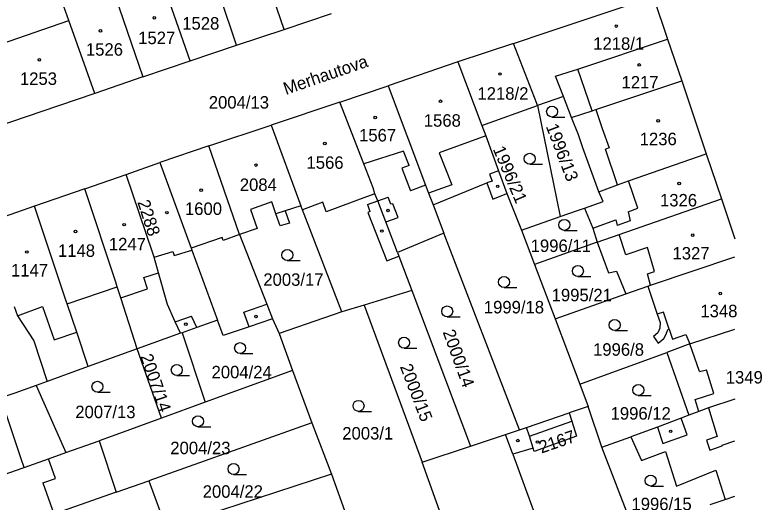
# Model space of a CAD drawing. Extents: x -564952 to -564307, y -1202373 to -1201847.
# Drawn here: x -564412.8 to -564310.9, y -1202215.7 to -1202149.3 of the extents above; entities that cross this region are included whole.
import ezdxf

# ---------------------------------------------------------------- set-up
doc = ezdxf.new("R2010")
doc.units = 0
for name, color, linetype in [('Hranice parcel', 7, 'Continuous'), ('Parcelní čísla', 7, 'Continuous'), ('Pop  PČ popisy', 7, 'Continuous'), ('Vnitřní kresba', 7, 'Continuous'), ('Značky budov', 7, 'Continuous'), ('Značky kultur', 7, 'Continuous')]:
    doc.layers.add(name, color=color, linetype=linetype)

msp = doc.modelspace()

# ---------------------------------------------------------------- linework, layer by layer
at = {"layer": 'Hranice parcel'}
for p, q in [((-564325.78, -1202146.73), (-564323.81, -1202152.55)), ((-564376.1, -1202151.25), (-564369.64, -1202149.05)), ((-564382.59, -1202153.39), (-564376.1, -1202151.25)), ((-564323.81, -1202152.55), (-564321.87, -1202158.24)), ((-564388.94, -1202155.54), (-564382.59, -1202153.39)), ((-564344.81, -1202153.14), (-564352.41, -1202155.68)), ((-564395.37, -1202157.69), (-564388.94, -1202155.54)), ((-564352.41, -1202155.68), (-564361.94, -1202158.92)), ((-564352.41, -1202155.68), (-564349.13, -1202164.34)), ((-564395.37, -1202157.69), (-564401.92, -1202159.96)), ((-564368.52, -1202161.14), (-564361.94, -1202158.92)), ((-564321.87, -1202158.24), (-564318.53, -1202168.2)), ((-564338.02, -1202160.39), (-564341.55, -1202161.62)), ((-564336.91, -1202163.24), (-564338.02, -1202160.39)), ((-564368.52, -1202161.14), (-564377.89, -1202164.3)), ((-564349.13, -1202164.34), (-564341.55, -1202161.62)), ((-564341.55, -1202161.62), (-564338.44, -1202176.75)), ((-564386.36, -1202167.12), (-564377.89, -1202164.3)), ((-564377.89, -1202164.3), (-564373.81, -1202175.3)), ((-564386.36, -1202167.12), (-564393.08, -1202169.4)), ((-564382.19, -1202179.19), (-564386.36, -1202167.12)), ((-564318.53, -1202168.2), (-564316.45, -1202174.31)), ((-564397.64, -1202171), (-564393.08, -1202169.4)), ((-564393.08, -1202169.4), (-564388.79, -1202181.06)), ((-564403.3, -1202172.98), (-564397.64, -1202171)), ((-564394.02, -1202181.72), (-564397.64, -1202171)), ((-564403.3, -1202172.98), (-564410.14, -1202175.34)), ((-564399.08, -1202185.67), (-564403.3, -1202172.98)), ((-564356.41, -1202173.55), (-564355.8, -1202175.14)), ((-564345.72, -1202173.6), (-564343.72, -1202178.62)), ((-564373.81, -1202175.3), (-564375.97, -1202175.98)), ((-564355.8, -1202175.14), (-564354.32, -1202179)), ((-564316.45, -1202174.31), (-564314.65, -1202179.77)), ((-564410.14, -1202175.34), (-564416.78, -1202177.62)), ((-564405.82, -1202188.28), (-564410.14, -1202175.34)), ((-564343.72, -1202178.62), (-564338.44, -1202176.75)), ((-564354.32, -1202179), (-564360.64, -1202181.66)), ((-564344.02, -1202205.84), (-564354.32, -1202179)), ((-564343.72, -1202178.62), (-564341.96, -1202183.28)), ((-564333.4, -1202180.24), (-564341.96, -1202183.28)), ((-564360.64, -1202181.66), (-564360.46, -1202182.13)), ((-564360.46, -1202182.13), (-564358.7, -1202186.81)), ((-564341.96, -1202183.28), (-564339.15, -1202190.71)), ((-564329.51, -1202187.3), (-564326.5, -1202186.24)), ((-564358.7, -1202186.81), (-564365.21, -1202188.81)), ((-564358.7, -1202186.81), (-564350.69, -1202208.05)), ((-564339.15, -1202190.71), (-564329.51, -1202187.3)), ((-564365.21, -1202188.81), (-564368.26, -1202189.75)), ((-564365.21, -1202188.81), (-564357.27, -1202210.21)), ((-564368.26, -1202189.75), (-564376.79, -1202192.67)), ((-564377.68, -1202190.7), (-564376.79, -1202192.67)), ((-564339.15, -1202190.71), (-564335.78, -1202199.6)), ((-564390.04, -1202192.58), (-564390.26, -1202192.66)), ((-564390.04, -1202192.58), (-564386.9, -1202202.07)), ((-564320.77, -1202194.12), (-564314.65, -1202192.1)), ((-564390.26, -1202192.66), (-564396.16, -1202194.76)), ((-564376.79, -1202192.67), (-564374.99, -1202197.73)), ((-564396.16, -1202194.76), (-564402.85, -1202197.21)), ((-564392.84, -1202204.24), (-564396.16, -1202194.76)), ((-564335.78, -1202199.6), (-564323.89, -1202195.26)), ((-564323.89, -1202195.26), (-564320.89, -1202203.83)), ((-564402.85, -1202197.21), (-564408.45, -1202199.22)), ((-564374.99, -1202197.73), (-564386.9, -1202202.07)), ((-564374.99, -1202197.73), (-564372.31, -1202204.85)), ((-564408.45, -1202199.22), (-564409.94, -1202199.76)), ((-564409.94, -1202199.76), (-564405.89, -1202208.93)), ((-564335.78, -1202199.6), (-564334.63, -1202202.63)), ((-564386.9, -1202202.07), (-564392.84, -1202204.24)), ((-564334.63, -1202202.63), (-564337.22, -1202203.52)), ((-564332.79, -1202208.17), (-564334.63, -1202202.63)), ((-564392.84, -1202204.24), (-564399.57, -1202206.7)), ((-564372.31, -1202204.85), (-564389.72, -1202211.06)), ((-564372.31, -1202204.85), (-564369.66, -1202211.88)), ((-564345.9, -1202206.48), (-564344.02, -1202205.84)), ((-564399.57, -1202206.7), (-564401.36, -1202207.34)), ((-564350.69, -1202208.05), (-564345.9, -1202206.48)), ((-564344.92, -1202209.13), (-564345.9, -1202206.48)), ((-564332.79, -1202208.17), (-564328.8, -1202206.76)), ((-564405.89, -1202208.93), (-564401.36, -1202207.34)), ((-564401.36, -1202207.34), (-564399.02, -1202214.32)), ((-564357.27, -1202210.21), (-564350.69, -1202208.05)), ((-564328.35, -1202219.63), (-564332.79, -1202208.17)), ((-564344.92, -1202209.13), (-564336.29, -1202232.6)), ((-564422.31, -1202214.68), (-564411.73, -1202210.99)), ((-564353.94, -1202219.47), (-564357.27, -1202210.21)), ((-564389.72, -1202211.06), (-564394.57, -1202212.76)), ((-564369.66, -1202211.88), (-564387.14, -1202217.59)), ((-564369.66, -1202211.88), (-564367.06, -1202219.05)), ((-564399.02, -1202214.32), (-564394.57, -1202212.76)), ((-564317.98, -1202216.02), (-564315.93, -1202215.31))]:
    msp.add_line(p, q, dxfattribs=at)
for points in [[(-564376.1, -1202151.25), (-564380.41, -1202138.65), (-564382.08, -1202134.54)], [(-564382.59, -1202153.39), (-564386.91, -1202140.5), (-564388.15, -1202137.47)], [(-564388.94, -1202155.54), (-564393.3, -1202143.04), (-564394.75, -1202139.64)], [(-564401.59, -1202140.42), (-564400.42, -1202143.26), (-564399.87, -1202144.59), (-564399.66, -1202145.21), (-564395.37, -1202157.69)], [(-564401.92, -1202159.96), (-564405.48, -1202150.04), (-564406.41, -1202147.46), (-564406.78, -1202146.53), (-564407.49, -1202144.77)], [(-564344.81, -1202153.14), (-564340.24, -1202151.6), (-564336.01, -1202150.19), (-564325.78, -1202146.73)], [(-564338.02, -1202160.39), (-564339.1, -1202157.6), (-564336.63, -1202156.83), (-564336.05, -1202156.64), (-564323.81, -1202152.55)], [(-564341.55, -1202161.62), (-564341.65, -1202161.36), (-564344.81, -1202153.14)], [(-564361.94, -1202158.92), (-564356.81, -1202172.49), (-564356.41, -1202173.55)], [(-564336.91, -1202163.24), (-564334.08, -1202162.32), (-564333.57, -1202162.15), (-564321.87, -1202158.24)], [(-564401.92, -1202159.96), (-564406.89, -1202161.65), (-564413.42, -1202163.87), (-564415.88, -1202164.71)], [(-564363.96, -1202172.83), (-564365.23, -1202169.56), (-564368.52, -1202161.14)], [(-564333.16, -1202173.36), (-564335.37, -1202167.37), (-564335.96, -1202165.63), (-564336.91, -1202163.24)], [(-564349.13, -1202164.34), (-564348.6, -1202165.74), (-564346.85, -1202170.52), (-564345.72, -1202173.6)], [(-564333.16, -1202173.36), (-564330.62, -1202172.43), (-564329.15, -1202171.9), (-564318.53, -1202168.2)], [(-564355.8, -1202175.14), (-564348.45, -1202172.16), (-564347.66, -1202174.38), (-564345.72, -1202173.6)], [(-564363.33, -1202174.6), (-564363.73, -1202173.64), (-564363.96, -1202172.83)], [(-564335.15, -1202175.59), (-564332.61, -1202174.69), (-564333.16, -1202173.36)], [(-564377.22, -1202176.37), (-564377.78, -1202174.76), (-564380.72, -1202175.77), (-564379.79, -1202178.36), (-564382.19, -1202179.19)], [(-564368.26, -1202189.75), (-564373.6, -1202175.84), (-564373.81, -1202175.3)], [(-564360.64, -1202181.66), (-564362.23, -1202177.48), (-564363.33, -1202174.6)], [(-564333.4, -1202180.24), (-564330.43, -1202179.2), (-564316.45, -1202174.31)], [(-564375.97, -1202175.98), (-564375.4, -1202177.63), (-564376.65, -1202178.02), (-564377.22, -1202176.37)], [(-564338.44, -1202176.75), (-564336.07, -1202175.91), (-564335.15, -1202175.59)], [(-564335.15, -1202175.59), (-564334.02, -1202178.32), (-564333.4, -1202180.24)], [(-564382.19, -1202179.19), (-564378.46, -1202188.71), (-564377.68, -1202190.7)], [(-564333.4, -1202180.24), (-564331.88, -1202184.42), (-564330.78, -1202184.21), (-564329.51, -1202187.3)], [(-564388.79, -1202181.06), (-564388.69, -1202181.33), (-564385.19, -1202190.86)], [(-564390.26, -1202192.66), (-564390.96, -1202191.11), (-564392.02, -1202188.74), (-564393.25, -1202184.4), (-564393.86, -1202182.27), (-564394.02, -1202181.72)], [(-564326.5, -1202186.24), (-564326.12, -1202186.1), (-564314.65, -1202182.22)], [(-564396.16, -1202194.76), (-564398.39, -1202187.82), (-564398.87, -1202186.32), (-564399.08, -1202185.67)], [(-564326.5, -1202186.24), (-564325.21, -1202190.06), (-564324.8, -1202191.17), (-564324.84, -1202191.95), (-564325.15, -1202192.62), (-564325.72, -1202193.11), (-564325.08, -1202194), (-564324.33, -1202193.39), (-564323.99, -1202192.78), (-564323.79, -1202192.16), (-564323.58, -1202192.12), (-564323.12, -1202193.45), (-564321.32, -1202192.84), (-564320.77, -1202194.12)], [(-564402.85, -1202197.21), (-564404.41, -1202192.51), (-564405.7, -1202188.65), (-564405.82, -1202188.28)], [(-564412.92, -1202189.01), (-564412.48, -1202190.3), (-564410.26, -1202193.68), (-564408.45, -1202199.22)], [(-564385.19, -1202190.86), (-564388.02, -1202191.86), (-564390.04, -1202192.58)], [(-564377.68, -1202190.7), (-564380.86, -1202191.77), (-564384.41, -1202192.97), (-564385.19, -1202190.86)], [(-564320.77, -1202194.12), (-564322.8, -1202194.86), (-564323.89, -1202195.26)], [(-564409.94, -1202199.76), (-564412.86, -1202200.81), (-564413, -1202200.86), (-564414.77, -1202201.48), (-564425.49, -1202205.25)], [(-564314.65, -1202201.64), (-564318.24, -1202202.82), (-564319.52, -1202203.31), (-564320.89, -1202203.83)], [(-564337.22, -1202203.52), (-564336.87, -1202204.62), (-564336.23, -1202206.68), (-564342, -1202208.78), (-564342.14, -1202208.33), (-564344.92, -1202209.13)], [(-564344.02, -1202205.84), (-564343.03, -1202205.5), (-564337.22, -1202203.52)], [(-564320.89, -1202203.83), (-564321.93, -1202204.23), (-564325.19, -1202205.48), (-564328.8, -1202206.76)], [(-564328.8, -1202206.76), (-564327.36, -1202210.02), (-564324.11, -1202208.79), (-564322.6, -1202213.51), (-564317.24, -1202211.33), (-564315.93, -1202215.31)], [(-564411.73, -1202210.99), (-564411.58, -1202210.94), (-564408.24, -1202209.76), (-564405.89, -1202208.93)], [(-564394.57, -1202212.76), (-564393.05, -1202216.87), (-564392.13, -1202219.38)], [(-564399.02, -1202214.32), (-564407.15, -1202217.16), (-564407.53, -1202217.29), (-564419.91, -1202221.63)], [(-564315.93, -1202215.31), (-564314.65, -1202214.86)]]:
    msp.add_lwpolyline(points, dxfattribs=at)
at = {"layer": 'Vnitřní kresba'}
for p, q in [((-564414.78, -1202153.23), (-564405.48, -1202150.04)), ((-564334.08, -1202162.32), (-564336.05, -1202156.64)), ((-564333.57, -1202162.15), (-564332.75, -1202164.74)), ((-564332.75, -1202164.74), (-564331.79, -1202167.37)), ((-564348.6, -1202165.74), (-564354.98, -1202168.08)), ((-564359.81, -1202167.84), (-564365.23, -1202169.56)), ((-564359.06, -1202169.79), (-564359.81, -1202167.84)), ((-564354.98, -1202168.08), (-564353.25, -1202172.43)), ((-564331.79, -1202167.37), (-564332.27, -1202167.55)), ((-564330.62, -1202172.43), (-564332.27, -1202167.55)), ((-564359.06, -1202169.79), (-564360.07, -1202170.15)), ((-564360.07, -1202170.15), (-564358.88, -1202173.23)), ((-564346.85, -1202170.52), (-564348.1, -1202170.95)), ((-564348.1, -1202170.95), (-564347.74, -1202171.92)), ((-564347.74, -1202171.92), (-564348.45, -1202172.16)), ((-564327.84, -1202175.61), (-564329.15, -1202171.9)), ((-564356.81, -1202172.49), (-564358.88, -1202173.23)), ((-564353.25, -1202172.43), (-564356.41, -1202173.55)), ((-564364.86, -1202174.06), (-564370.36, -1202176.1)), ((-564363.73, -1202173.64), (-564364.86, -1202174.06)), ((-564363.33, -1202174.6), (-564361.94, -1202174.1)), ((-564361.56, -1202175.07), (-564361.94, -1202174.1)), ((-564370.85, -1202174.78), (-564373.6, -1202175.84)), ((-564370.36, -1202176.1), (-564370.85, -1202174.78)), ((-564364.76, -1202175.12), (-564363.33, -1202174.6)), ((-564364.76, -1202175.12), (-564364.43, -1202176.05)), ((-564361.28, -1202175), (-564361.56, -1202175.07)), ((-564360.56, -1202176.87), (-564361.28, -1202175)), ((-564375.97, -1202175.98), (-564377.22, -1202176.37)), ((-564364.43, -1202176.05), (-564364.69, -1202176.19)), ((-564364.69, -1202176.19), (-564362.1, -1202182.77)), ((-564329.18, -1202176.09), (-564327.84, -1202175.61)), ((-564329.18, -1202176.09), (-564328.9, -1202177.32)), ((-564362.23, -1202177.48), (-564360.56, -1202176.87)), ((-564334.02, -1202178.32), (-564330.87, -1202177.21)), ((-564330.87, -1202177.21), (-564330.67, -1202177.95)), ((-564328.9, -1202177.32), (-564330.67, -1202177.95)), ((-564382.19, -1202179.19), (-564384.44, -1202179.99)), ((-564329.52, -1202181.98), (-564330.43, -1202179.2)), ((-564384.57, -1202179.61), (-564388.79, -1202181.06)), ((-564384.44, -1202179.99), (-564384.57, -1202179.61)), ((-564391.13, -1202182.04), (-564388.69, -1202181.33)), ((-564326.55, -1202180.97), (-564329.52, -1202181.98)), ((-564325.58, -1202184.26), (-564326.55, -1202180.97)), ((-564393.86, -1202182.27), (-564391.28, -1202181.52)), ((-564391.28, -1202181.52), (-564391.13, -1202182.04)), ((-564362.1, -1202182.77), (-564360.46, -1202182.13)), ((-564395.23, -1202185.07), (-564393.25, -1202184.4)), ((-564326.55, -1202184.56), (-564325.58, -1202184.26)), ((-564394.74, -1202186.58), (-564395.23, -1202185.07)), ((-564326.12, -1202186.1), (-564326.55, -1202184.56)), ((-564405.7, -1202188.65), (-564398.87, -1202186.32)), ((-564398.39, -1202187.82), (-564394.74, -1202186.58)), ((-564412.48, -1202190.3), (-564409.08, -1202189)), ((-564409.08, -1202189), (-564407.47, -1202193.55)), ((-564381.6, -1202189.76), (-564378.46, -1202188.71)), ((-564390.96, -1202191.11), (-564388.74, -1202190.32)), ((-564388.02, -1202191.86), (-564388.74, -1202190.32)), ((-564380.86, -1202191.77), (-564381.6, -1202189.76)), ((-564324.35, -1202189.77), (-564325.21, -1202190.06)), ((-564323.58, -1202192.12), (-564324.35, -1202189.77)), ((-564407.47, -1202193.55), (-564404.41, -1202192.51)), ((-564319.47, -1202197.88), (-564320.77, -1202194.12)), ((-564319.47, -1202197.88), (-564318.51, -1202197.62)), ((-564317.49, -1202200.86), (-564318.51, -1202197.62)), ((-564411.97, -1202209.79), (-564414.77, -1202201.48)), ((-564320.03, -1202201.7), (-564317.49, -1202200.86)), ((-564319.52, -1202203.31), (-564320.03, -1202201.7)), ((-564318.24, -1202202.82), (-564317.04, -1202206.75)), ((-564342.66, -1202206.67), (-564336.87, -1202204.62)), ((-564321.12, -1202206.5), (-564321.93, -1202204.23)), ((-564342.66, -1202206.67), (-564343.03, -1202205.5)), ((-564325.19, -1202205.48), (-564324.43, -1202207.69)), ((-564342.14, -1202208.33), (-564342.66, -1202206.67)), ((-564324.43, -1202207.69), (-564321.12, -1202206.5)), ((-564317.04, -1202206.75), (-564318.48, -1202207.25)), ((-564318.48, -1202207.25), (-564318.03, -1202208.59)), ((-564316.36, -1202207.92), (-564314.65, -1202207.32)), ((-564316.34, -1202208), (-564316.36, -1202207.92)), ((-564318.03, -1202208.59), (-564316.34, -1202208)), ((-564411.58, -1202210.94), (-564411.97, -1202209.79)), ((-564407.29, -1202212.45), (-564408.24, -1202209.76)), ((-564409.02, -1202213.06), (-564407.29, -1202212.45)), ((-564409.02, -1202213.06), (-564407.53, -1202217.29))]:
    msp.add_line(p, q, dxfattribs=at)
at = {"layer": 'Značky budov'}
for centre in [(-564393.82, -1202149.66), (-564330.8, -1202150.78), (-564401.17, -1202151.43), (-564409.5, -1202155.39), (-564327.68, -1202156.08), (-564346.66, -1202157.32), (-564354.78, -1202161.03), (-564363.68, -1202163.24), (-564325.09, -1202163.7), (-564370.56, -1202166.78), (-564379.95, -1202169.73), (-564322.23, -1202172.24), (-564387.43, -1202173.15), (-564346.98, -1202172.63), (-564392.1, -1202176.22), (-564361.94, -1202175.93), (-564397.93, -1202177.86), (-564404.57, -1202178.79), (-564362.78, -1202178.72), (-564320.38, -1202179.29), (-564411.2, -1202181.58), (-564316.61, -1202187.23), (-564379.95, -1202190.37), (-564389.51, -1202191.41), (-564323.38, -1202206.02), (-564344.23, -1202207.29), (-564341.55, -1202207.48)]:
    msp.add_circle(centre, 0.175, dxfattribs=at)
at = {"layer": 'Značky kultur'}
for p, q in [((-564339.56, -1202163.19), (-564337.81, -1202163.19)), ((-564342.61, -1202169.62), (-564340.86, -1202169.62)), ((-564337.89, -1202178.63), (-564336.14, -1202178.63)), ((-564375.68, -1202182.74), (-564373.93, -1202182.74)), ((-564336.04, -1202184.92), (-564334.29, -1202184.92)), ((-564346.11, -1202186.42), (-564344.36, -1202186.42)), ((-564353.87, -1202190.43), (-564352.12, -1202190.43)), ((-564331.02, -1202192.29), (-564329.27, -1202192.29)), ((-564382.12, -1202195.43), (-564380.37, -1202195.43)), ((-564359.75, -1202194.69), (-564358, -1202194.69)), ((-564390.75, -1202198.41), (-564389, -1202198.41)), ((-564401.58, -1202200.7), (-564399.83, -1202200.7)), ((-564327.8, -1202201.15), (-564326.05, -1202201.15)), ((-564365.96, -1202203.3), (-564364.21, -1202203.3)), ((-564387.86, -1202205.4), (-564386.11, -1202205.4)), ((-564383.01, -1202211.91), (-564381.26, -1202211.91)), ((-564326.11, -1202213.49), (-564324.36, -1202213.49))]:
    msp.add_line(p, q, dxfattribs=at)
for centre in [(-564339.56, -1202162.44), (-564342.61, -1202168.87), (-564337.89, -1202177.88), (-564375.68, -1202181.99), (-564336.04, -1202184.17), (-564346.11, -1202185.67), (-564353.87, -1202189.68), (-564331.02, -1202191.54), (-564359.75, -1202193.94), (-564382.12, -1202194.68), (-564390.75, -1202197.66), (-564401.58, -1202199.95), (-564327.8, -1202200.4), (-564365.96, -1202202.55), (-564387.86, -1202204.65), (-564383.01, -1202211.16), (-564326.11, -1202212.74)]:
    msp.add_circle(centre, 0.75, dxfattribs=at)

# ---------------------------------------------------------------- texts
at = {"layer": 'Parcelní čísla'}
for s, p in [('1528', (-564390.01, -1202151.26)), ('1527', (-564396.02, -1202153.24)), ('1218/1', (-564333.95, -1202154.02)), ('1526', (-564403.15, -1202154.82)), ('1253', (-564412.15, -1202158.8)), ('1217', (-564330.09, -1202159.29)), ('1218/2', (-564349.74, -1202160.82)), ('2004/13', (-564386.39, -1202162.03)), ('1568', (-564357.06, -1202164.5)), ('1567', (-564365.89, -1202166.51)), ('1236', (-564327.61, -1202167.02)), ('1566', (-564373.06, -1202170.24)), ('2084', (-564382.16, -1202173.26)), ('1326', (-564324.84, -1202175.37)), ('1600', (-564389.64, -1202176.53)), ('1247', (-564400.02, -1202181.35)), ('1996/11', (-564342.48, -1202181.58)), ('1148', (-564406.96, -1202182.24)), ('1327', (-564323.13, -1202182.6)), ('1147', (-564413.37, -1202184.92)), ('2003/17', (-564378.95, -1202186.19)), ('1995/21', (-564339.62, -1202188.3)), ('1999/18', (-564348.87, -1202189.95)), ('1348', (-564319.33, -1202190.47)), ('1996/8', (-564333.97, -1202195.72)), ('2004/24', (-564386.01, -1202198.8)), ('1349', (-564315.87, -1202199.51)), ('2007/13', (-564404.6, -1202204.23)), ('1996/12', (-564331.58, -1202204.43)), ('2003/1', (-564368.18, -1202207.14)), ('2004/23', (-564391.64, -1202209.14)), ('2004/22', (-564387.22, -1202215.08)), ('1996/15', (-564328.73, -1202216.78))]:
    msp.add_text(s, height=1.7, dxfattribs=at).set_placement(p)
for s, rotation, p in [('1996/13', 291, (-564340.44, -1202164.45)), ('1996/21', 293, (-564347.67, -1202167.55)), ('2288', 288, (-564396.15, -1202174.77)), ('2000/14', 290, (-564354.5, -1202192.49)), ('2007/14', 289, (-564395.75, -1202195.8)), ('2000/15', 291, (-564360.34, -1202197.2)), ('2167', 19, (-564341.01, -1202209.06))]:
    msp.add_text(s, height=1.7, rotation=rotation, dxfattribs=at).set_placement(p)
at = {"layer": 'Pop  PČ popisy'}
msp.add_text('Merhautova', height=1.7, rotation=19, dxfattribs=at).set_placement((-564375.87, -1202160.18))

doc.saveas('drawing.dxf')
